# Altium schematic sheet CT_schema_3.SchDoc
size 315 x 177 mm
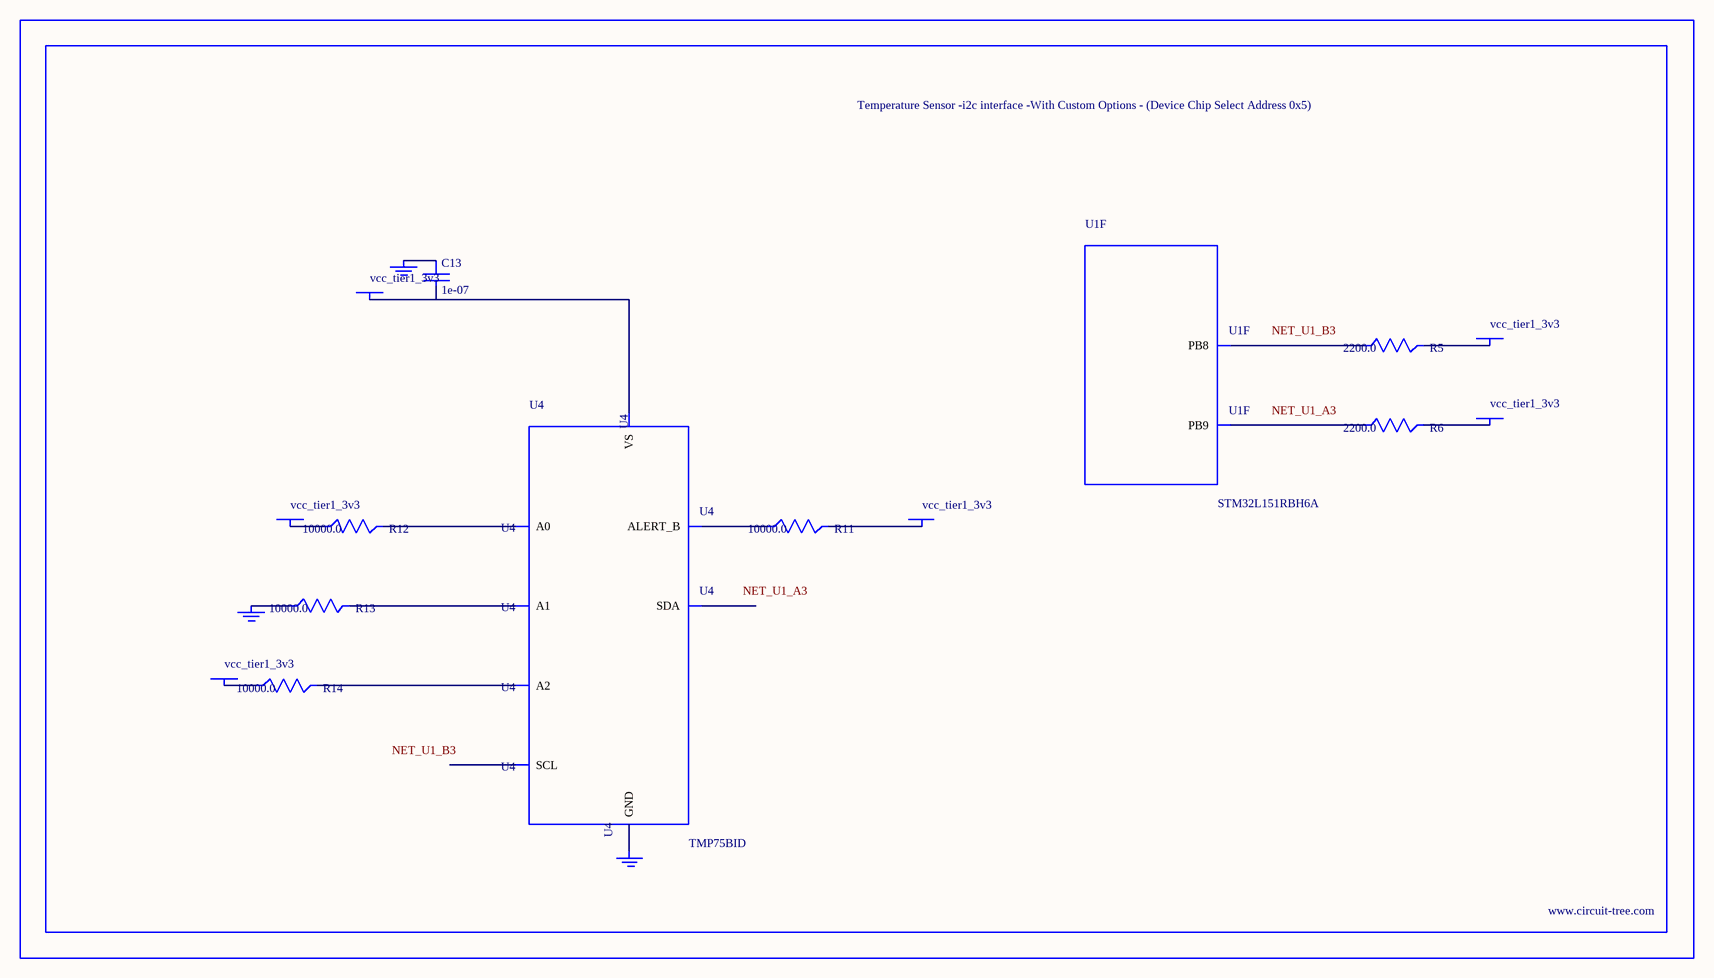
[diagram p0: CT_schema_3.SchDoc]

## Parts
BORDER2  (no value)
C13  1e-07  [C0402]
GND_INSTANCE_2_0  (no value)
GND_INSTANCE_2_1  (no value)
GND_INSTANCE_2_2  (no value)
POWER_INSTANCE_2_0  vcc_tier1_3v3
POWER_INSTANCE_2_1  vcc_tier1_3v3
POWER_INSTANCE_2_2  vcc_tier1_3v3
POWER_INSTANCE_2_3  vcc_tier1_3v3
POWER_INSTANCE_2_4  vcc_tier1_3v3
POWER_INSTANCE_2_5  vcc_tier1_3v3
R5  2200.0  [R0603]
R6  2200.0  [R0603]
R11  10000.0  [R0603]
R12  10000.0  [R0603]
R13  10000.0  [R0603]
R14  10000.0  [R0603]
U1  STM32L151RBH6A  [TFBGA64]  (part F of 6)
U4  TMP75BID  [SOIC-8]

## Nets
NetC13_1: C13.1 GND_INSTANCE_2_1.0(GND)
NetC13_2: C13.2 POWER_INSTANCE_2_3.0(PWR) U4.8(VS)
NetGND_INSTANCE_2_0_0: GND_INSTANCE_2_0.0(GND) R13.1
NetGND_INSTANCE_2_2_0: GND_INSTANCE_2_2.0(GND) U4.4(GND)
NetPOWER_INSTANCE_2_0_0: POWER_INSTANCE_2_0.0(PWR) R11.2
NetPOWER_INSTANCE_2_1_0: POWER_INSTANCE_2_1.0(PWR) R14.1
NetPOWER_INSTANCE_2_2_0: POWER_INSTANCE_2_2.0(PWR) R12.1
NetPOWER_INSTANCE_2_4_0: POWER_INSTANCE_2_4.0(PWR) R5.2
NetPOWER_INSTANCE_2_5_0: POWER_INSTANCE_2_5.0(PWR) R6.2
NetR5_1: R5.1 U1.B3(PB8)
NetR6_1: R6.1 U1.A3(PB9)
NetR11_1: R11.1 U4.3(ALERT_B)
NetR12_2: R12.2 U4.7(A0)
NetR13_2: R13.2 U4.6(A1)
NetR14_2: R14.2 U4.5(A2)

Not connected (* = marked no-connect by the designer): U4 1(SDA) 2(SCL)

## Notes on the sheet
- Labels drawn without touching a wire or pin: NET_U1_A3, NET_U1_B3

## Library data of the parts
BORDER2 = BORDER_PAGE2
C13 = C0402C104K3RACTU
GND_INSTANCE_2_0-GND_INSTANCE_2_2 = GND
POWER_INSTANCE_2_0-POWER_INSTANCE_2_5 = PWR
R5 R6 = RC0603JR-072K2L
R11-R14 = RC0603JR-0710KL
